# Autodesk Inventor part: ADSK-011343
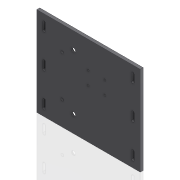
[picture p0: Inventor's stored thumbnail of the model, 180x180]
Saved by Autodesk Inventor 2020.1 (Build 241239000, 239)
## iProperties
Created: 1999-12
Part Number: ADSK-011343
Material: Acier doux
Description: PLT-66,FH,CP,03,140,120,MNT,SHAFT,VERT
Document SubType Name: Modeling
Designer: sspink
Density: 7.86 g/cm^3
Appearance: Metal-Steel(Polish)
Mass: 8278.12 g
Surface Area: 2311.81 cm^2
Volume: 1053.2 cm^3
Control State: 0
Checked Out: False
Master: False
Shininess: 0.0
Length Units: 11269
Angle Units: 11279
Time Units: 11290
Mass Units: 11283
Length Display Precision: 3
Angle Display Precision: 2
Compacted: True
Dimensions: 354x305x10 mm
Mass: 8,278 kg
DocNumber: ADSK-011343.ipt
Folder: 01 - Themengebiete\Simplification\01 - Packaging machine\
VDS_Category: 3D Komponenten
Density: 0.0
Volumn: 0.0
Area: 0.0
PropertySet Name: Model Information
Author: sspink
Revision Number: -
Title: PLT-66,FH,CP,03,140,120,MNT,SHAFT,VERT
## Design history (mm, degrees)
node "Rectangular Pattern1" dims "d23" = 20, "d25" = 304
node "Solide1"
  node "Extrusion1" dims "d2" = 10, "d3" = 0
  node "Hole1" dims "d8" = 13.5, "d9" = 28, "d10" = 6.35, "d11" = 90 deg, "d12" = 19.05, "d13" = 118 deg, "d53" = 6
  node "Extrusion2" dims "d20" = 9.525, "d21" = 0
  node "Hole2" dims "d32" = 6.647, "d33" = 9.525, "d34" = 6.35, "d35" = 60 deg, "d36" = 19.05, "d37" = 118 deg, "d55" = 16
  node "Hole3" dims "d47" = 9, "d48" = 17.3, "d49" = 9, "d50" = 90 deg, "d51" = 19.05, "d52" = 118 deg, "d56" = 6
sketch "Sketch1"
  geometry: L1 (13.736, 713.332)-(13.736, 1018.332) reference; L2 (13.736, 1018.332)-(-340.264, 1018.332) reference; L3 (-340.264, 1018.332)-(-340.264, 713.332); L4 (-340.264, 713.332)-(13.736, 713.332)
  constraints: 8 end point, 2 perpendicular, 2 vertical, 1 horizontal, 1 parallel
  dimensions: "d0" = 305 distance of L1.start L1.end; "d1" = 354 distance between parallel lines of L3 L1
sketch "Sketch2"
  geometry: L1 (13.736, 1018.332)-(13.736, 713.332) reference; L2 (-340.264, 1018.332)-(13.736, 1018.332) reference; L3 (-340.264, 713.332)-(-340.264, 1018.332) reference; L4 (13.736, 713.332)-(-340.264, 713.332) reference; L5 (-214.864, 960.832)-(-214.864, 770.832); 4 further points
  constraints: 2 coincident, 2 end point, 2 midpoint, 1 horizontal alignment, 1 vertical, 1 vertical alignment
  dimensions: "d43" = 228.6 distance from line of point (-214.864, 960.832) L1; "d57" = 190 distance of point (-214.864, 770.832) point (-214.864, 960.832)
sketch "Sketch5"
  geometry: L1 (-13.736, 713.332)-(-13.736, 1018.332) reference; L2 (340.264, 1018.332)-(340.264, 713.332) reference; L3 (-13.736, 865.832)-(340.264, 865.832); 2 further points
  constraints: 2 end point, 2 midpoint, 1 vertical alignment
  dimensions: "d44" = 70 distance from line of point (252.864, 935.832) L3; "d45" = 70 distance from line of L3 point (252.864, 795.832) (= d44); "d46" = 87.4 distance from line of point (252.864, 795.832) L2
sketch "Sketch3"
  geometry: L1 (13.736, 1018.332)-(13.736, 713.332) reference; L2 (-316.464, 1018.332)-(13.736, 1018.332) reference; L3 (-15.764, 993.332)-(-6.764, 993.332); L4 (-6.764, 993.332)-(-6.764, 968.332); L5 (-6.764, 968.332)-(-15.764, 968.332); L6 (-15.764, 968.332)-(-15.764, 993.332); L7 (-15.764, 878.332)-(-6.764, 878.332); L8 (-6.764, 878.332)-(-6.764, 853.332); L9 (-6.764, 853.332)-(-15.764, 853.332); L10 (-15.764, 853.332)-(-15.764, 878.332); L11 (-15.764, 763.332)-(-6.764, 763.332); L12 (-6.764, 763.332)-(-6.764, 738.332); L13 (-6.764, 738.332)-(-15.764, 738.332); L14 (-15.764, 738.332)-(-15.764, 763.332); A1 r 4.5 centre (-11.264, 993.332) between (-6.764, 993.332) and (-15.764, 993.332); A2 r 4.5 centre (-11.264, 968.332) between (-15.764, 968.332) and (-6.764, 968.332); A3 r 4.5 centre (-11.264, 878.332) between (-6.764, 878.332) and (-15.764, 878.332); A4 r 4.5 centre (-11.264, 853.332) between (-15.764, 853.332) and (-6.764, 853.332); A5 r 4.5 centre (-11.264, 763.332) between (-6.764, 763.332) and (-15.764, 763.332); A6 r 4.5 centre (-11.264, 738.332) between (-15.764, 738.332) and (-6.764, 738.332); 3 further points; 1 other entity
  constraints: 24 end point, 12 point on circle, 6 centre point, 6 parallel, 6 tangent, 3 horizontal, 3 perpendicular, 2 collinear, 2 equal radius, 2 midpoint, 2 vertical alignment, 1 horizontal alignment, 1 other
  dimensions: "d14" = 4.5 radius of A1; "d15" = 25 distance of L3.end L4.end; "d16" = 25 distance from line of A6.centre L1; "d17" = 25 dimension on A6.centre; "d18" = 25 distance from line of A1.centre L2 (= d17)
sketch "Sketch4"
  geometry: L1 (-13.736, 713.332)-(-13.736, 1018.332) reference; L2 (-13.736, 1018.332)-(340.264, 1018.332) reference; 4 further points
  constraints: 2 horizontal alignment, 2 vertical alignment
  dimensions: "d29" = 92 distance from line of point (107.064, 926.332) L2; "d30" = 177.8 distance from line of point (164.064, 926.332) L1; "d40" = 45 distance of point (107.064, 881.332) point (107.064, 926.332); "d54" = 57 distance of point (164.064, 926.332) point (107.064, 926.332)
node "Corps solides"
node "Corps surfaciques"
